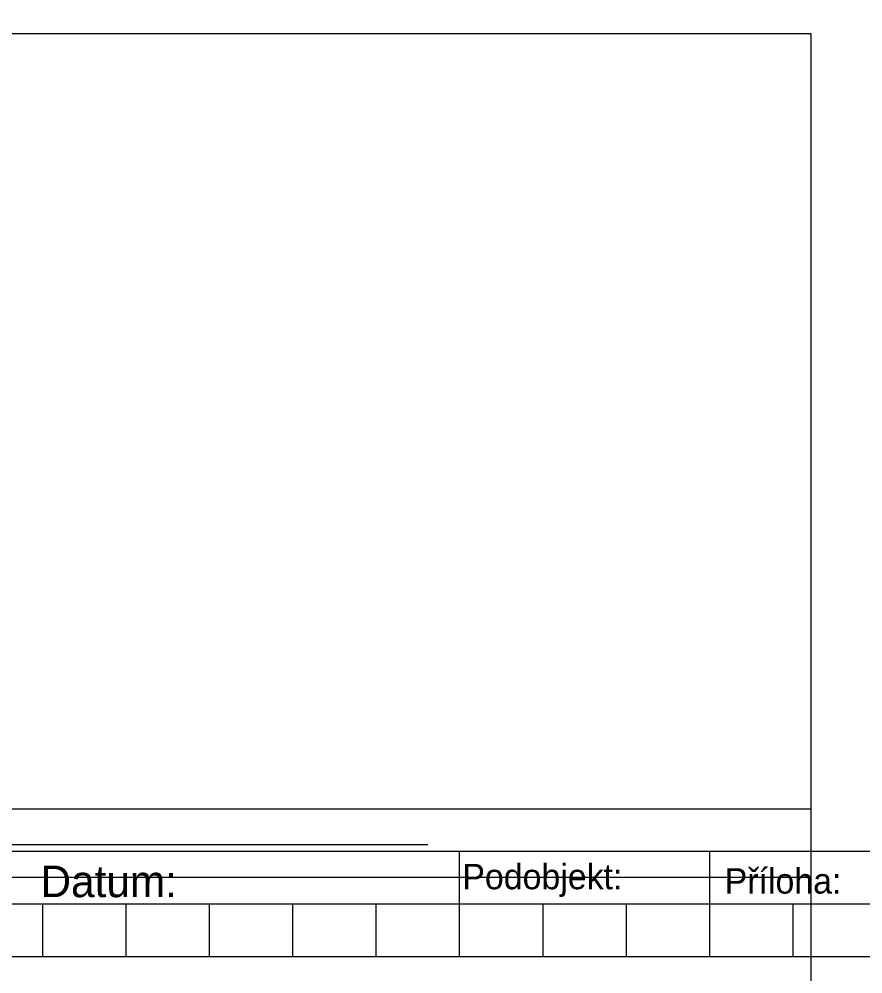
# Model space of a CAD drawing. Extents: x 1391 to 5528, y -6194 to 565.
# Drawn here: x 4157 to 4556.8, y -5834.6 to -5382.2 of the extents above; entities that cross this region are included whole.
import ezdxf

# ---------------------------------------------------------------- set-up
doc = ezdxf.new("R2010")
doc.units = 0
for name, color, linetype in [('Vrstva 2', 7, 'Continuous'), ('Vrstva 3', 7, 'Continuous'), ('Vrstva 8', 7, 'Continuous')]:
    doc.layers.add(name, color=color, linetype=linetype)

# ---------------------------------------------------------------- blocks, each defined once
blk = doc.blocks.new('_U1')
at = {"layer": 'Vrstva 8'}
for p, q in [((3.35, 0.25), (3.35, -0.25)), ((4.535, 0.25), (4.535, -0.25)), ((8.5, 0), (-8.5, 0)), ((1.375, 0), (1.375, -0.25)), ((1.77, 0), (1.77, -0.25)), ((2.165, 0), (2.165, -0.25)), ((2.56, 0), (2.56, -0.25)), ((2.955, 0), (2.955, -0.25)), ((3.745, 0), (3.745, -0.25)), ((4.14, 0), (4.14, -0.25)), ((4.93, 0), (4.93, -0.25))]:
    blk.add_line(p, q, dxfattribs=at)
blk.add_lwpolyline([(-8.5, 0.25), (8.5, 0.25), (8.5, -0.25), (-8.5, -0.25)], close=True, dxfattribs=at)
for s, p in [('Podobjekt:', (3.3643, 0.0699)), ('Příloha:', (4.6073, 0.0493))]:
    blk.add_text(s, height=0.12, dxfattribs=at).set_placement(p)
blk = doc.blocks.new('_U2')
at = {"layer": 'Vrstva 3'}
blk.add_line((-2.6675, -1.82505), (2.6675, -1.82505), dxfattribs=at)
for s, p in [('Razítko oprávněné osoby:', (-2.5675, 1.92495)), ('Podpis:', (-2.5675, -2.07505)), ('Datum:', (0.8325, -2.07505))]:
    blk.add_text(s, height=0.15, dxfattribs=at).set_placement(p)
blk = doc.blocks.new('_U3')
at = {"layer": 'Vrstva 2'}
blk.add_lwpolyline([(-5.33255, 2.00005), (5.33245, 2.00005), (5.33245, -1.99995), (-5.33255, -1.99995)], close=True, dxfattribs=at)

msp = doc.modelspace()

# ---------------------------------------------------------------- block references
at = {"layer": 'Vrstva 2', "xscale": 100, "yscale": 100}
for p in [(3998.89, -5589.03), (3998.89, -5956.45)]:
    msp.add_blockref('_U3', p, dxfattribs=at)
at = {"layer": 'Vrstva 3', "xscale": 100, "yscale": 100}
for p in [(4083.89, -5590.78), (4083.89, -5958.2)]:
    msp.add_blockref('_U2', p, dxfattribs=at)
at = {"layer": 'Vrstva 8', "xscale": 100, "yscale": 100}
msp.add_blockref('_U1', (4030.56, -5801.53), dxfattribs=at)

doc.saveas('drawing.dxf')
